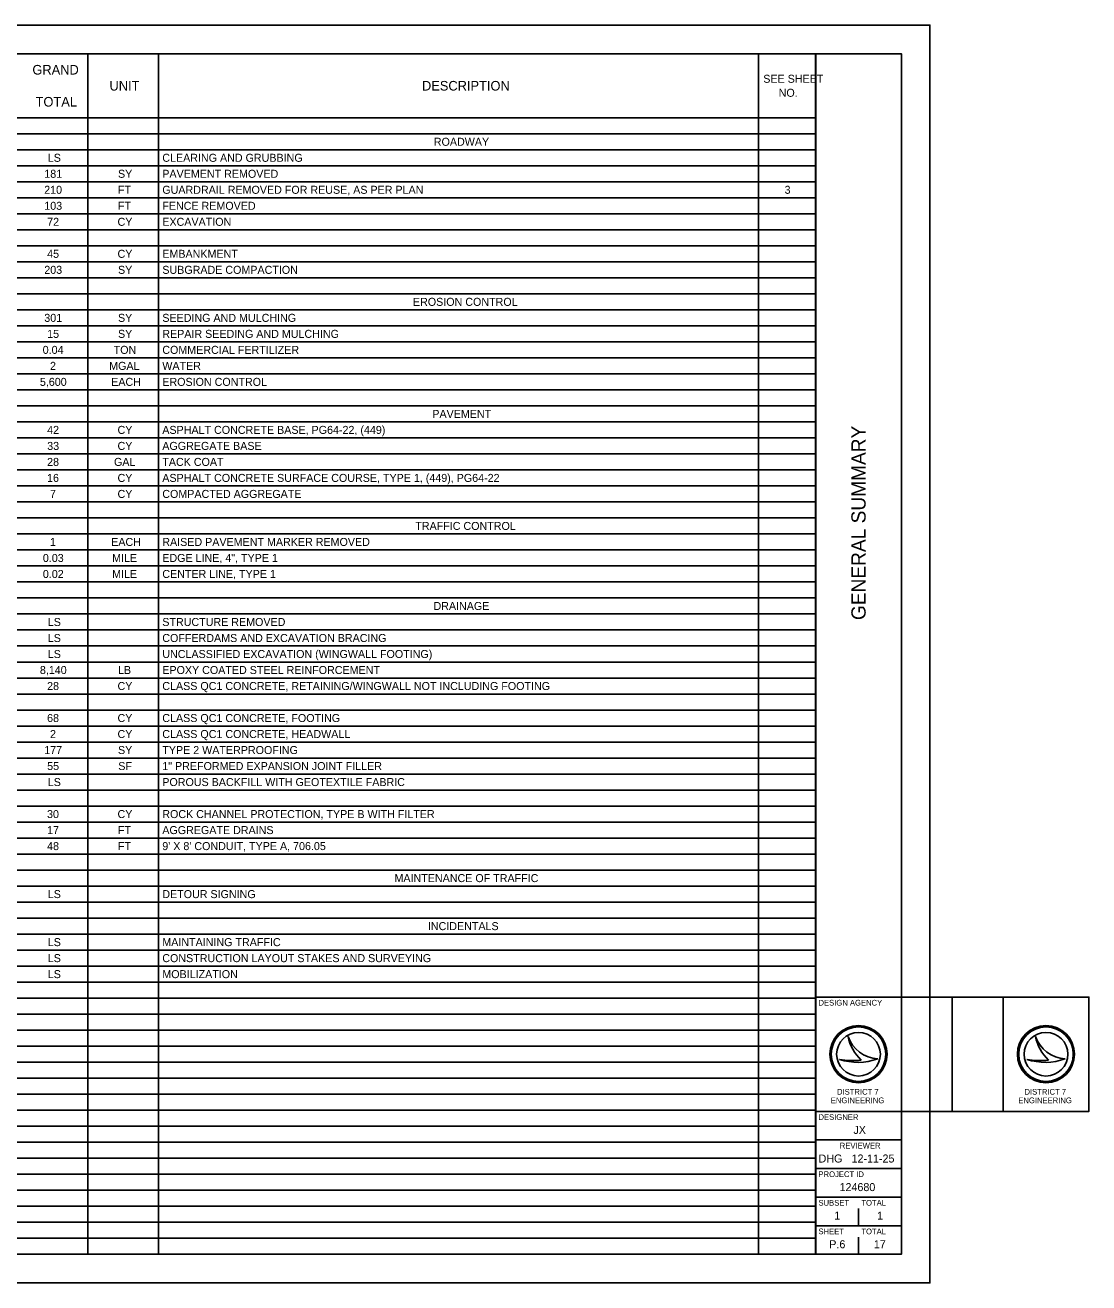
# Model space of a CAD drawing. Extents: x 0 to 36.8, y 0 to 22.
# Drawn here: x 18.17 to 36.78, y 0 to 22 of the extents above; entities that cross this region are included whole.
import ezdxf

# ---------------------------------------------------------------- set-up
doc = ezdxf.new("R2010")
doc.units = 0
for name, color, linetype in [('SC_Scratch1', 7, 'Continuous'), ('SH_Border', 7, 'Continuous'), ('SH_Cut_Line', 7, 'Continuous'), ('SH_Data', 7, 'Continuous'), ('SH_Text', 7, 'Continuous')]:
    doc.layers.add(name, color=color, linetype=linetype)

msp = doc.modelspace()

# ---------------------------------------------------------------- linework, layer by layer
at = {"layer": 'SC_Scratch1'}
for p, q in [((33.5, 5), (35.279, 5)), ((34.389, 5), (34.389, 3)), ((35.279, 3), (33.5, 3))]:
    msp.add_line(p, q, dxfattribs=at)
msp.add_lwpolyline([(35.279, 5), (36.779, 5), (36.779, 3), (35.279, 3)], close=True, dxfattribs=at)
at = {"layer": 'SH_Border'}
for p, q in [((32, 0.5), (32, 21.5)), ((32, 5), (33.5, 5)), ((32, 3), (33.5, 3)), ((32, 2.5), (33.5, 2.5)), ((32, 2), (33.5, 2)), ((32, 1.5), (33.5, 1.5)), ((32, 1), (33.5, 1))]:
    msp.add_line(p, q, dxfattribs=at)
msp.add_lwpolyline([(1.5, 21.5), (33.5, 21.5), (33.5, 0.5), (1.5, 0.5)], close=True, dxfattribs=at)
at = {"layer": 'SH_Cut_Line'}
msp.add_lwpolyline([(0, 0), (34, 0), (34, 22), (0, 22)], close=True, dxfattribs=at)
at = {"layer": 'SH_Data'}
for p, q in [((1.5, 21.5), (32.004, 21.5)), ((19.272, 21.5), (19.272, 0.5)), ((20.507, 21.5), (20.507, 0.5)), ((30.999, 21.5), (30.999, 0.5)), ((32.004, 21.5), (32.004, 0.5)), ((1.5, 20.38), (32.004, 20.38)), ((1.5, 20.1), (32.004, 20.1)), ((1.5, 19.82), (32.004, 19.82)), ((1.5, 19.54), (32.004, 19.54)), ((1.5, 19.26), (32.004, 19.26)), ((1.5, 18.98), (32.004, 18.98)), ((1.5, 18.7), (32.004, 18.7)), ((1.5, 18.42), (32.004, 18.42)), ((1.5, 18.14), (32.004, 18.14)), ((1.5, 17.86), (32.004, 17.86)), ((1.5, 17.58), (32.004, 17.58)), ((1.5, 17.3), (32.004, 17.3)), ((1.5, 17.02), (32.004, 17.02)), ((1.5, 16.74), (32.004, 16.74)), ((1.5, 16.46), (32.004, 16.46)), ((1.5, 16.18), (32.004, 16.18)), ((1.5, 15.9), (32.004, 15.9)), ((1.5, 15.62), (32.004, 15.62)), ((1.5, 15.34), (32.004, 15.34)), ((1.5, 15.06), (32.004, 15.06)), ((1.5, 14.78), (32.004, 14.78)), ((1.5, 14.5), (32.004, 14.5)), ((1.5, 14.22), (32.004, 14.22)), ((1.5, 13.94), (32.004, 13.94)), ((1.5, 13.66), (32.004, 13.66)), ((1.5, 13.38), (32.004, 13.38)), ((1.5, 13.1), (32.004, 13.1)), ((1.5, 12.82), (32.004, 12.82)), ((1.5, 12.54), (32.004, 12.54)), ((1.5, 12.26), (32.004, 12.26)), ((1.5, 11.98), (32.004, 11.98)), ((1.5, 11.7), (32.004, 11.7)), ((1.5, 11.42), (32.004, 11.42)), ((1.5, 11.14), (32.004, 11.14)), ((1.5, 10.86), (32.004, 10.86)), ((1.5, 10.58), (32.004, 10.58)), ((1.5, 10.3), (32.004, 10.3)), ((1.5, 10.02), (32.004, 10.02)), ((1.5, 9.74), (32.004, 9.74)), ((1.5, 9.46), (32.004, 9.46)), ((1.5, 9.18), (32.004, 9.18)), ((1.5, 8.9), (32.004, 8.9)), ((1.5, 8.62), (32.004, 8.62)), ((1.5, 8.34), (32.004, 8.34)), ((1.5, 8.06), (32.004, 8.06)), ((1.5, 7.78), (32.004, 7.78)), ((1.5, 7.5), (32.004, 7.5)), ((1.5, 7.22), (32.004, 7.22)), ((1.5, 6.94), (32.004, 6.94)), ((1.5, 6.66), (32.004, 6.66)), ((1.5, 6.38), (32.004, 6.38)), ((1.5, 6.1), (32.004, 6.1)), ((1.5, 5.82), (32.004, 5.82)), ((1.5, 5.54), (32.004, 5.54)), ((1.5, 5.26), (32.004, 5.26)), ((1.5, 4.98), (32.004, 4.98)), ((1.5, 4.7), (32.004, 4.7)), ((1.5, 4.42), (32.004, 4.42)), ((32.567, 4.31), (32.567, 4.31)), ((35.846, 4.31), (35.846, 4.31)), ((1.5, 4.14), (32.004, 4.14)), ((32.75, 4), (32.75, 4)), ((1.5, 3.86), (32.004, 3.86)), ((32.417, 3.91), (32.417, 3.91)), ((33.087, 3.919), (33.087, 3.919)), ((35.696, 3.91), (35.696, 3.91)), ((36.366, 3.919), (36.366, 3.919)), ((1.5, 3.58), (32.004, 3.58)), ((1.5, 3.3), (32.004, 3.3)), ((1.5, 3.02), (32.004, 3.02)), ((1.5, 2.74), (32.004, 2.74)), ((1.5, 2.46), (32.004, 2.46)), ((1.5, 2.18), (32.004, 2.18)), ((1.5, 1.9), (32.004, 1.9)), ((1.5, 1.62), (32.004, 1.62)), ((1.5, 1.34), (32.004, 1.34)), ((32.75, 1), (32.75, 1.3)), ((1.5, 1.06), (32.004, 1.06)), ((1.5, 0.78), (32.004, 0.78)), ((32.375, 0.675), (32.375, 0.675)), ((32.75, 0.5), (32.75, 0.8)), ((1.5, 0.5), (32.004, 0.5))]:
    msp.add_line(p, q, dxfattribs=at)
for centre, radius in [((32.75, 4), 0.5), ((32.75, 4), 0.477), ((32.75, 4), 0.477), ((36.029, 4), 0.5), ((36.029, 4), 0.477), ((36.029, 4), 0.477), ((32.75, 4), 0.382), ((36.029, 4), 0.382)]:
    msp.add_circle(centre, radius, dxfattribs=at)
for centre, radius, start, end in [((33.116, 4.498), 0.58, 198.9257, 198.9319), ((33.347, 4.47), 0.796, 191.6379, 191.6421), ((33.116, 4.498), 0.58, 198.9319, 267.1657), ((33.347, 4.47), 0.796, 191.6421, 226.0947), ((36.395, 4.498), 0.58, 198.9257, 198.9319), ((36.625, 4.47), 0.796, 191.6379, 191.6421), ((36.395, 4.498), 0.58, 198.9319, 267.1657), ((36.625, 4.47), 0.796, 191.6421, 226.0947), ((32.739, 4.87), 1.013, 251.4576, 290.0832), ((32.648, 5.154), 1.266, 259.4964, 259.4995), ((32.739, 4.87), 1.013, 251.4527, 251.4576), ((32.648, 5.154), 1.266, 259.4995, 276.6672), ((36.018, 4.87), 1.013, 251.4576, 290.0832), ((35.927, 5.154), 1.266, 259.4964, 259.4995), ((36.018, 4.87), 1.013, 251.4527, 251.4576), ((35.927, 5.154), 1.266, 259.4995, 276.6672)]:
    msp.add_arc(centre, radius, start, end, dxfattribs=at)

# ---------------------------------------------------------------- texts
msp.add_text('GENERAL SUMMARY', height=0.25, rotation=90, dxfattribs=at).set_placement((32.875, 11.594))
for s, height, p in [('DESIGN AGENCY', 0.1, (32.05, 4.85)), ('DESIGNER', 0.1, (32.05, 2.85)), ('JX', 0.14, (32.661, 2.605)), ('REVIEWER', 0.1, (32.422, 2.35)), ('DHG', 0.14, (32.052, 2.105)), ('12-11-25', 0.14, (32.629, 2.105)), ('PROJECT ID', 0.1, (32.05, 1.85)), ('SUBSET', 0.1, (32.05, 1.35)), ('TOTAL', 0.1, (32.8, 1.35)), ('1', 0.14, (32.325, 1.105)), ('1', 0.14, (33.075, 1.105)), ('SHEET', 0.1, (32.05, 0.85)), ('TOTAL', 0.1, (32.8, 0.85)), ('P.6', 0.14, (32.239, 0.605)), ('17', 0.14, (33.018, 0.605))]:
    msp.add_text(s, height=height, dxfattribs=at).set_placement(p)
at = {"layer": 'SH_Text'}
for s, height, p in [('GRAND', 0.168, (18.301, 21.136)), ('SEE SHEET ', 0.14, (31.084, 20.992)), ('UNIT', 0.168, (19.649, 20.856)), ('DESCRIPTION', 0.168, (25.115, 20.856)), ('TOTAL', 0.168, (18.357, 20.576)), ('NO.', 0.14, (31.354, 20.747)), ('ROADWAY', 0.14, (25.322, 19.89)), ('LS', 0.14, (18.57, 19.61)), ('CLEARING AND GRUBBING', 0.14, (20.573, 19.61)), ('181', 0.14, (18.509, 19.33)), ('SY', 0.14, (19.798, 19.33)), ('PAVEMENT REMOVED', 0.14, (20.573, 19.33)), ('210', 0.14, (18.507, 19.05)), ('FT', 0.14, (19.796, 19.05)), ('GUARDRAIL REMOVED FOR REUSE, AS PER PLAN', 0.14, (20.573, 19.05)), ('3', 0.14, (31.457, 19.05)), ('103', 0.14, (18.509, 18.77)), ('FT', 0.14, (19.796, 18.77)), ('FENCE REMOVED', 0.14, (20.573, 18.77)), ('72', 0.14, (18.559, 18.49)), ('CY', 0.14, (19.79, 18.49)), ('EXCAVATION', 0.14, (20.573, 18.49)), ('45', 0.14, (18.559, 17.93)), ('CY', 0.14, (19.79, 17.93)), ('EMBANKMENT', 0.14, (20.573, 17.93)), ('203', 0.14, (18.509, 17.65)), ('SY', 0.14, (19.798, 17.65)), ('SUBGRADE COMPACTION', 0.14, (20.573, 17.65)), ('EROSION CONTROL', 0.14, (24.957, 17.09)), ('301', 0.14, (18.509, 16.81)), ('SY', 0.14, (19.798, 16.81)), ('SEEDING AND MULCHING', 0.14, (20.573, 16.81)), ('15', 0.14, (18.559, 16.53)), ('SY', 0.14, (19.798, 16.53)), ('REPAIR SEEDING AND MULCHING', 0.14, (20.573, 16.53)), ('0.04', 0.14, (18.481, 16.25)), ('TON', 0.14, (19.722, 16.25)), ('COMMERCIAL FERTILIZER', 0.14, (20.573, 16.25)), ('2', 0.14, (18.609, 15.97)), ('MGAL', 0.14, (19.644, 15.97)), ('WATER', 0.14, (20.573, 15.97)), ('5,600', 0.14, (18.432, 15.69)), ('EACH', 0.14, (19.679, 15.69)), ('EROSION CONTROL', 0.14, (20.573, 15.69)), ('PAVEMENT', 0.14, (25.296, 15.13)), ('42', 0.14, (18.559, 14.85)), ('CY', 0.14, (19.79, 14.85)), ('ASPHALT CONCRETE BASE, PG64-22, (449)', 0.14, (20.573, 14.85)), ('33', 0.14, (18.56, 14.57)), ('CY', 0.14, (19.79, 14.57)), ('AGGREGATE BASE', 0.14, (20.573, 14.57)), ('28', 0.14, (18.558, 14.29)), ('GAL', 0.14, (19.728, 14.29)), ('TACK COAT', 0.14, (20.573, 14.29)), ('16', 0.14, (18.557, 14.01)), ('CY', 0.14, (19.79, 14.01)), ('ASPHALT CONCRETE SURFACE COURSE, TYPE 1, (449), PG64-22', 0.14, (20.573, 14.01)), ('7', 0.14, (18.608, 13.73)), ('CY', 0.14, (19.79, 13.73)), ('COMPACTED AGGREGATE', 0.14, (20.573, 13.73)), ('TRAFFIC CONTROL', 0.14, (24.998, 13.17)), ('1', 0.14, (18.609, 12.89)), ('EACH', 0.14, (19.679, 12.89)), ('RAISED PAVEMENT MARKER REMOVED', 0.14, (20.573, 12.89)), ('0.03', 0.14, (18.484, 12.61)), ('MILE', 0.14, (19.695, 12.61)), ('EDGE LINE, 4", TYPE 1', 0.14, (20.573, 12.61)), ('0.02', 0.14, (18.484, 12.33)), ('MILE', 0.14, (19.695, 12.33)), ('CENTER LINE, TYPE 1', 0.14, (20.573, 12.33)), ('DRAINAGE', 0.14, (25.316, 11.77)), ('LS', 0.14, (18.57, 11.49)), ('STRUCTURE REMOVED', 0.14, (20.573, 11.49)), ('LS', 0.14, (18.57, 11.21)), ('COFFERDAMS AND EXCAVATION BRACING', 0.14, (20.573, 11.21)), ('LS', 0.14, (18.57, 10.93)), ('UNCLASSIFIED EXCAVATION (WINGWALL FOOTING)', 0.14, (20.573, 10.93)), ('8,140', 0.14, (18.432, 10.65)), ('LB', 0.14, (19.798, 10.65)), ('EPOXY COATED STEEL REINFORCEMENT', 0.14, (20.573, 10.65)), ('28', 0.14, (18.558, 10.37)), ('CY', 0.14, (19.79, 10.37)), ('CLASS QC1 CONCRETE, RETAINING/WINGWALL NOT INCLUDING FOOTING', 0.14, (20.573, 10.37)), ('68', 0.14, (18.558, 9.81)), ('CY', 0.14, (19.79, 9.81)), ('CLASS QC1 CONCRETE, FOOTING', 0.14, (20.573, 9.81)), ('2', 0.14, (18.609, 9.53)), ('CY', 0.14, (19.79, 9.53)), ('CLASS QC1 CONCRETE, HEADWALL', 0.14, (20.573, 9.53)), ('177', 0.14, (18.508, 9.25)), ('SY', 0.14, (19.798, 9.25)), ('TYPE 2 WATERPROOFING', 0.14, (20.573, 9.25)), ('55', 0.14, (18.559, 8.97)), ('SF', 0.14, (19.803, 8.97)), ('1" PREFORMED EXPANSION JOINT FILLER', 0.14, (20.573, 8.97)), ('LS', 0.14, (18.57, 8.69)), ('POROUS BACKFILL WITH GEOTEXTILE FABRIC', 0.14, (20.573, 8.69)), ('30', 0.14, (18.557, 8.13)), ('CY', 0.14, (19.79, 8.13)), ('ROCK CHANNEL PROTECTION, TYPE B WITH FILTER', 0.14, (20.573, 8.13)), ('17', 0.14, (18.558, 7.85)), ('FT', 0.14, (19.796, 7.85)), ('AGGREGATE DRAINS', 0.14, (20.573, 7.85)), ('48', 0.14, (18.558, 7.57)), ('FT', 0.14, (19.796, 7.57)), ("9' X 8' CONDUIT, TYPE A, 706.05", 0.14, (20.573, 7.57)), ('MAINTENANCE OF TRAFFIC', 0.14, (24.634, 7.01)), ('LS', 0.14, (18.57, 6.73)), ('DETOUR SIGNING', 0.14, (20.573, 6.73)), ('INCIDENTALS', 0.14, (25.218, 6.17)), ('LS', 0.14, (18.57, 5.89)), ('MAINTAINING TRAFFIC', 0.14, (20.573, 5.89)), ('LS', 0.14, (18.57, 5.61)), ('CONSTRUCTION LAYOUT STAKES AND SURVEYING', 0.14, (20.573, 5.61)), ('LS', 0.14, (18.57, 5.33)), ('MOBILIZATION', 0.14, (20.573, 5.33)), ('DISTRICT 7', 0.1, (32.374, 3.292)), ('DISTRICT 7', 0.1, (35.653, 3.292)), ('ENGINEERING', 0.1, (32.265, 3.142)), ('ENGINEERING', 0.1, (35.544, 3.142)), ('124680', 0.14, (32.419, 1.605))]:
    msp.add_text(s, height=height, dxfattribs=at).set_placement(p)

doc.saveas('drawing.dxf')
